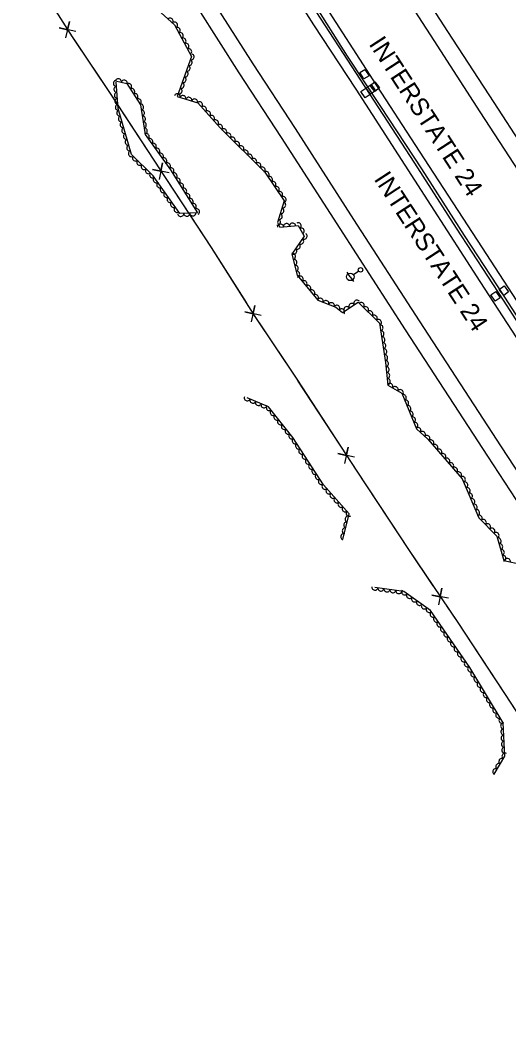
# Model space of a CAD drawing. Extents: x 1746719 to 1766531, y 631721 to 662391.
# Drawn here: x 1758351 to 1758675, y 643107 to 643775 of the extents above; entities that cross this region are included whole.
import ezdxf

# ---------------------------------------------------------------- set-up
doc = ezdxf.new("R2010")
doc.units = 0
for name, color, linetype in [('SURVEY - AERIAL SURVEY - Photo Control - Points - Elevations', 7, 'Continuous'), ('SURVEY - AERIAL SURVEY - Photo Control - Points - Numbers', 7, 'Continuous'), ('SURVEY - AERIAL SURVEY - Photo Control with Text', 7, 'Continuous'), ('SURVEY - CENTERLINE - Existing Roads - Development', 7, 'Continuous'), ('SURVEY - CENTERLINE - Existing Roads Curve Text', 7, 'Continuous'), ('SURVEY - CENTERLINE - Preliminary Curve Text', 7, 'Continuous'), ('SURVEY - CONTROL - Points - Numbers', 7, 'Continuous')]:
    doc.layers.add(name, color=color, linetype=linetype)

msp = doc.modelspace()

# ---------------------------------------------------------------- linework, layer by layer
at = {"layer": 'SURVEY - AERIAL SURVEY - Photo Control - Points - Elevations'}
for points in [[(1758528.06, 643931.93), (1758563.85, 643876.61), (1758601.12, 643819.25), (1758634.52, 643767.49), (1758665.16, 643720.35), (1758703.51, 643661.29), (1758738.55, 643607.32), (1758780.47, 643542.02), (1758810.94, 643495.12), (1758838.28, 643453.17), (1758866.99, 643408.66), (1758892.36, 643369.61), (1758923.55, 643321.11), (1758957.87, 643268.54), (1758994.04, 643213.01), (1759028.02, 643160.29), (1759080.26, 643078.92)], [(1758518.82, 643925.96), (1758554.62, 643870.63), (1758591.89, 643813.27), (1758625.29, 643761.51), (1758655.94, 643714.35), (1758694.29, 643655.3), (1758729.31, 643601.35), (1758771.23, 643536.05), (1758801.72, 643489.13), (1758829.05, 643447.19), (1758857.76, 643402.68), (1758883.12, 643363.64), (1758914.32, 643315.13), (1758948.66, 643262.53), (1758984.81, 643207.03), (1759018.77, 643154.33), (1759063.92, 643084.02)], [(1758478.52, 643899.88), (1758514.34, 643844.52), (1758551.6, 643787.18), (1758585, 643735.42), (1758615.69, 643688.2), (1758654.03, 643629.16), (1758688.99, 643575.32), (1758730.91, 643510.01), (1758761.49, 643462.94), (1758788.78, 643421.08), (1758817.46, 643376.6), (1758842.81, 643337.58), (1758874.04, 643289.02), (1758908.45, 643236.31), (1758944.53, 643180.93), (1758978.4, 643128.37), (1758991.56, 643107.86)], [(1758468.3, 643892.82), (1758518.79, 643814.29), (1758545.64, 643772.07), (1758573.58, 643729.23), (1758612.52, 643668.88), (1758655.85, 643601.7), (1758710.28, 643518.17), (1758755.48, 643448.9), (1758787.26, 643399.75), (1758819.19, 643350.04), (1758852.01, 643299.36), (1758884.04, 643250.16), (1758916.85, 643199.48), (1758947.08, 643151.96), (1758968.19, 643118.54), (1758971.32, 643114.19)], [(1758418.68, 643860.91), (1758469.08, 643782.51), (1758496.04, 643740.12), (1758524.08, 643697.13), (1758562.94, 643636.89), (1758606.35, 643569.6), (1758660.86, 643485.94), (1758706, 643416.76), (1758737.66, 643367.79), (1758769.61, 643318.06), (1758802.52, 643267.23), (1758834.56, 643218.03), (1758867.2, 643167.62), (1758883.89, 643141.38)], [(1758427.93, 643866.86), (1758478.35, 643788.43), (1758505.29, 643746.07), (1758533.31, 643703.11), (1758572.18, 643642.86), (1758615.58, 643575.58), (1758670.07, 643491.95), (1758715.22, 643422.76), (1758746.91, 643373.75), (1758778.85, 643324.02), (1758811.75, 643273.22), (1758843.78, 643224.02), (1758876.46, 643173.56), (1758900.11, 643136.38)]]:
    msp.add_lwpolyline(points, dxfattribs=at)
at = {"layer": 'SURVEY - AERIAL SURVEY - Photo Control - Points - Numbers'}
for points in [[(1758472.93, 643895.91), (1758511.15, 643837.03), (1758541.32, 643789.92), (1758579.58, 643730.89), (1758612.54, 643680.31), (1758640.13, 643637.02), (1758671.38, 643589.3), (1758696.06, 643550.94), (1758734.52, 643491.6), (1758769.46, 643437.46), (1758798.96, 643391.67), (1758828.14, 643347.01), (1758855.82, 643304.89), (1758888.58, 643253.95), (1758919.89, 643205.82), (1758952.75, 643155.4), (1758965.25, 643135.33), (1758978.51, 643110.86)], [(1758474.42, 643896.69), (1758499.1, 643858.3), (1758522.7, 643822.19), (1758544.63, 643788), (1758567.84, 643751.26), (1758589.99, 643717.73), (1758617.15, 643676.37), (1758645.44, 643632.14), (1758667.24, 643598.9), (1758699.36, 643549.24), (1758720.79, 643516.12), (1758745.17, 643478.53), (1758765.34, 643446.49), (1758792.97, 643404.34), (1758817.4, 643366.56), (1758846.78, 643320.84), (1758873.44, 643280.56), (1758895.52, 643246.69), (1758919.66, 643209.23), (1758944.42, 643171.53), (1758969.21, 643133.78), (1758984.79, 643110.37)]]:
    msp.add_lwpolyline(points, dxfattribs=at)
at = {"layer": 'SURVEY - AERIAL SURVEY - Photo Control with Text'}
for points in [[(1758435.74, 643787.95), (1758453.41, 643771.98), (1758464.62, 643750.96), (1758455.18, 643724.33), (1758468.97, 643720.23), (1758483.59, 643703.6), (1758513.21, 643674.18), (1758526.06, 643655.24), (1758521.72, 643640.92), (1758523.21, 643637.84), (1758535.42, 643638.92), (1758539.41, 643631.73), (1758531.29, 643619.91), (1758534.75, 643605.82), (1758548.43, 643589.38), (1758560.33, 643584.66), (1758564.73, 643581.25), (1758575.15, 643588.02), (1758589.31, 643574.05), (1758593.32, 643548.08), (1758594.82, 643533.04), (1758604.05, 643527.55), (1758613.76, 643504.02), (1758621.39, 643497.16), (1758644.23, 643470.72), (1758655.21, 643445), (1758667.15, 643432.88), (1758671.7, 643416.63), (1758684.01, 643414.05)], [(1758414.26, 643734.79), (1758421.69, 643733.15), (1758430.78, 643718.86), (1758433.83, 643699.15), (1758450.77, 643675.7), (1758468.58, 643647.25), (1758456.96, 643646.73), (1758439.28, 643671.92), (1758424.85, 643686.07), (1758416.12, 643716.58), (1758414.67, 643733.96)], [(1758565.06, 643430.47), (1758569.31, 643447.56), (1758552.21, 643466.74), (1758531.82, 643498.33), (1758515.75, 643518.51), (1758501.53, 643524.47)], [(1758665.29, 643274.82), (1758672.43, 643286.87), (1758671.43, 643308.95), (1758649.11, 643345.7), (1758623.16, 643383.41), (1758605.51, 643396.05), (1758586.15, 643398.83)]]:
    msp.add_lwpolyline(points, dxfattribs=at)
for centre, major_axis in [((1758450.54, 643774.58), (1.48, -1.34)), ((1758453.47, 643771.88), (0.94, -1.76)), ((1758455.35, 643768.35), (0.94, -1.76)), ((1758457.24, 643764.82), (0.94, -1.76)), ((1758459.12, 643761.29), (0.94, -1.76)), ((1758461, 643757.76), (0.94, -1.76)), ((1758462.88, 643754.23), (0.94, -1.76)), ((1758463.19, 643746.91), (-0.67, -1.88)), ((1758464.52, 643750.68), (-0.67, -1.88)), ((1758460.51, 643739.37), (-0.67, -1.88)), ((1758461.85, 643743.14), (-0.67, -1.88)), ((1758414.74, 643733.19), (-0.17, 1.99)), ((1758416.21, 643734.36), (1.95, -0.43)), ((1758420.11, 643733.49), (1.95, -0.43)), ((1758422.97, 643731.13), (1.07, -1.69)), ((1758457.84, 643731.83), (-0.67, -1.88)), ((1758459.18, 643735.6), (-0.67, -1.88)), ((1758415.07, 643729.21), (-0.17, 1.99)), ((1758415.4, 643725.22), (-0.17, 1.99)), ((1758425.12, 643727.76), (1.07, -1.69)), ((1758456.5, 643728.06), (-0.67, -1.88)), ((1758415.74, 643721.23), (-0.17, 1.99)), ((1758427.27, 643724.39), (1.07, -1.69)), ((1758429.42, 643721.01), (1.07, -1.69)), ((1758455.22, 643724.32), (1.92, -0.57)), ((1758459.05, 643723.18), (1.92, -0.57)), ((1758462.89, 643722.04), (1.92, -0.57)), ((1758466.72, 643720.9), (1.92, -0.57)), ((1758470.06, 643718.99), (1.32, -1.5)), ((1758416.07, 643717.25), (-0.17, 1.99)), ((1758417.04, 643713.38), (-0.55, 1.92)), ((1758431, 643717.43), (0.31, -1.98)), ((1758431.61, 643713.47), (0.31, -1.98)), ((1758472.7, 643715.98), (1.32, -1.5)), ((1758475.34, 643712.98), (1.32, -1.5)), ((1758418.14, 643709.53), (-0.55, 1.92)), ((1758419.24, 643705.69), (-0.55, 1.92)), ((1758432.22, 643709.52), (0.31, -1.98)), ((1758432.83, 643705.57), (0.31, -1.98)), ((1758477.99, 643709.97), (1.32, -1.5)), ((1758480.63, 643706.97), (1.32, -1.5)), ((1758420.34, 643701.84), (-0.55, 1.92)), ((1758433.44, 643701.61), (0.31, -1.98)), ((1758434.71, 643697.93), (1.17, -1.62)), ((1758483.27, 643703.97), (1.32, -1.5)), ((1758486.08, 643701.13), (1.42, -1.41)), ((1758488.92, 643698.31), (1.42, -1.41)), ((1758421.44, 643698), (-0.55, 1.92)), ((1758422.54, 643694.15), (-0.55, 1.92)), ((1758437.05, 643694.69), (1.17, -1.62)), ((1758439.39, 643691.44), (1.17, -1.62)), ((1758491.76, 643695.49), (1.42, -1.41)), ((1758494.6, 643692.67), (1.42, -1.41)), ((1758423.64, 643690.3), (-0.55, 1.92)), ((1758424.74, 643686.46), (-0.55, 1.92)), ((1758441.73, 643688.2), (1.17, -1.62)), ((1758444.08, 643684.96), (1.17, -1.62)), ((1758497.43, 643689.85), (1.42, -1.41)), ((1758500.27, 643687.03), (1.42, -1.41)), ((1758427.42, 643683.55), (-1.43, 1.4)), ((1758430.27, 643680.75), (-1.43, 1.4)), ((1758446.42, 643681.72), (1.17, -1.62)), ((1758448.76, 643678.48), (1.17, -1.62)), ((1758503.11, 643684.21), (1.42, -1.41)), ((1758505.95, 643681.39), (1.42, -1.41)), ((1758508.79, 643678.58), (1.42, -1.41)), ((1758433.13, 643677.95), (-1.43, 1.4)), ((1758435.99, 643675.15), (-1.43, 1.4)), ((1758438.84, 643672.35), (-1.43, 1.4)), ((1758451.07, 643675.21), (1.06, -1.7)), ((1758453.2, 643671.82), (1.06, -1.7)), ((1758511.62, 643675.76), (1.42, -1.41)), ((1758514.2, 643672.72), (1.12, -1.66)), ((1758441.23, 643669.15), (-1.15, 1.64)), ((1758443.52, 643665.87), (-1.15, 1.64)), ((1758455.32, 643668.43), (1.06, -1.7)), ((1758457.44, 643665.04), (1.06, -1.7)), ((1758516.45, 643669.41), (1.12, -1.66)), ((1758518.69, 643666.1), (1.12, -1.66)), ((1758445.82, 643662.6), (-1.15, 1.64)), ((1758448.12, 643659.33), (-1.15, 1.64)), ((1758459.56, 643661.65), (1.06, -1.7)), ((1758461.69, 643658.26), (1.06, -1.7)), ((1758520.94, 643662.79), (1.12, -1.66)), ((1758523.18, 643659.48), (1.12, -1.66)), ((1758450.42, 643656.05), (-1.15, 1.64)), ((1758452.72, 643652.78), (-1.15, 1.64)), ((1758463.81, 643654.87), (1.06, -1.7)), ((1758465.93, 643651.48), (1.06, -1.7)), ((1758525.43, 643656.17), (1.12, -1.66)), ((1758525.22, 643652.49), (-0.58, -1.91)), ((1758455.01, 643649.51), (-1.15, 1.64)), ((1758457.57, 643646.76), (-2, -0.09)), ((1758461.57, 643646.94), (-2, -0.09)), ((1758465.57, 643647.12), (-2, -0.09)), ((1758468.05, 643648.09), (1.06, -1.7)), ((1758522.9, 643644.83), (-0.58, -1.91)), ((1758524.06, 643648.66), (-0.58, -1.91)), ((1758521.74, 643641), (-0.58, -1.91)), ((1758527.69, 643638.24), (1.99, 0.17)), ((1758531.67, 643638.59), (1.99, 0.17)), ((1758535.54, 643638.71), (0.97, -1.75)), ((1758523.71, 643637.89), (1.99, 0.17)), ((1758537.48, 643635.21), (0.97, -1.75)), ((1758539.39, 643631.71), (-1.13, -1.65)), ((1758534.87, 643625.11), (-1.13, -1.65)), ((1758537.13, 643628.41), (-1.13, -1.65)), ((1758531.69, 643618.27), (0.48, -1.94)), ((1758532.6, 643621.82), (-1.13, -1.65)), ((1758532.65, 643614.39), (0.48, -1.94)), ((1758533.6, 643610.5), (0.48, -1.94)), ((1758534.55, 643606.62), (0.48, -1.94)), ((1758536.78, 643603.38), (1.28, -1.54)), ((1758539.34, 643600.3), (1.28, -1.54)), ((1758541.9, 643597.23), (1.28, -1.54)), ((1758544.46, 643594.15), (1.28, -1.54)), ((1758547.01, 643591.08), (1.28, -1.54)), ((1758550.09, 643588.72), (1.86, -0.74)), ((1758553.81, 643587.24), (1.86, -0.74)), ((1758557.53, 643585.77), (1.86, -0.74)), ((1758570.95, 643585.29), (1.68, 1.09)), ((1758574.3, 643587.47), (1.68, 1.09)), ((1758577.28, 643585.92), (1.42, -1.4)), ((1758561.11, 643584.05), (1.58, -1.23)), ((1758564.27, 643581.6), (1.58, -1.23)), ((1758567.59, 643583.11), (1.68, 1.09)), ((1758580.13, 643583.11), (1.42, -1.4)), ((1758582.97, 643580.3), (1.42, -1.4)), ((1758585.82, 643577.49), (1.42, -1.4)), ((1758588.67, 643574.68), (1.42, -1.4)), ((1758589.78, 643570.98), (0.31, -1.98)), ((1758590.39, 643567.03), (0.31, -1.98)), ((1758591, 643563.08), (0.31, -1.98)), ((1758591.61, 643559.13), (0.31, -1.98)), ((1758592.22, 643555.17), (0.31, -1.98)), ((1758592.83, 643551.22), (0.31, -1.98)), ((1758593.4, 643547.26), (0.2, -1.99)), ((1758593.8, 643543.28), (0.2, -1.99)), ((1758594.2, 643539.3), (0.2, -1.99)), ((1758594.59, 643535.32), (0.2, -1.99)), ((1758596.29, 643532.16), (1.72, -1.02)), ((1758599.73, 643530.12), (1.72, -1.02)), ((1758603.16, 643528.07), (1.72, -1.02)), ((1758605.18, 643524.8), (0.76, -1.85)), ((1758501.64, 643524.43), (-1.84, 0.77)), ((1758505.33, 643522.88), (-1.84, 0.77)), ((1758509.02, 643521.33), (-1.84, 0.77)), ((1758512.71, 643519.79), (-1.84, 0.77)), ((1758606.71, 643521.1), (0.76, -1.85)), ((1758516.19, 643517.97), (-1.25, 1.56)), ((1758518.68, 643514.84), (-1.25, 1.56)), ((1758521.17, 643511.71), (-1.25, 1.56)), ((1758608.23, 643517.41), (0.76, -1.85)), ((1758609.76, 643513.71), (0.76, -1.85)), ((1758523.66, 643508.58), (-1.25, 1.56)), ((1758526.16, 643505.45), (-1.25, 1.56)), ((1758611.29, 643510.01), (0.76, -1.85)), ((1758612.81, 643506.32), (0.76, -1.85)), ((1758528.65, 643502.32), (-1.25, 1.56)), ((1758531.14, 643499.19), (-1.25, 1.56)), ((1758614.89, 643503.01), (1.49, -1.34)), ((1758617.86, 643500.33), (1.49, -1.34)), ((1758620.84, 643497.65), (1.49, -1.34)), ((1758533.4, 643495.89), (-1.08, 1.68)), ((1758535.57, 643492.53), (-1.08, 1.68)), ((1758623.52, 643494.69), (1.31, -1.51)), ((1758626.13, 643491.67), (1.31, -1.51)), ((1758537.73, 643489.17), (-1.08, 1.68)), ((1758539.9, 643485.81), (-1.08, 1.68)), ((1758628.75, 643488.64), (1.31, -1.51)), ((1758631.36, 643485.61), (1.31, -1.51)), ((1758542.07, 643482.45), (-1.08, 1.68)), ((1758544.24, 643479.09), (-1.08, 1.68)), ((1758633.98, 643482.59), (1.31, -1.51)), ((1758636.59, 643479.56), (1.31, -1.51)), ((1758546.41, 643475.73), (-1.08, 1.68)), ((1758548.58, 643472.37), (-1.08, 1.68)), ((1758639.21, 643476.53), (1.31, -1.51)), ((1758641.82, 643473.51), (1.31, -1.51)), ((1758550.75, 643469.01), (-1.08, 1.68)), ((1758553.08, 643465.77), (-1.33, 1.49)), ((1758644.36, 643470.43), (0.79, -1.84)), ((1758645.93, 643466.75), (0.79, -1.84)), ((1758555.74, 643462.78), (-1.33, 1.49)), ((1758558.4, 643459.79), (-1.33, 1.49)), ((1758647.5, 643463.07), (0.79, -1.84)), ((1758649.07, 643459.39), (0.79, -1.84)), ((1758561.06, 643456.81), (-1.33, 1.49)), ((1758563.72, 643453.82), (-1.33, 1.49)), ((1758650.64, 643455.71), (0.79, -1.84)), ((1758652.21, 643452.03), (0.79, -1.84)), ((1758566.39, 643450.84), (-1.33, 1.49)), ((1758568.44, 643444.06), (0.48, 1.94)), ((1758569.05, 643447.85), (-1.33, 1.49)), ((1758653.78, 643448.35), (0.79, -1.84)), ((1758655.46, 643444.75), (1.4, -1.42)), ((1758567.48, 643440.18), (0.48, 1.94)), ((1758658.26, 643441.9), (1.4, -1.42)), ((1758661.07, 643439.05), (1.4, -1.42)), ((1758565.55, 643432.41), (0.48, 1.94)), ((1758566.51, 643436.3), (0.48, 1.94)), ((1758663.88, 643436.2), (1.4, -1.42)), ((1758666.68, 643433.35), (1.4, -1.42)), ((1758668.05, 643429.66), (0.54, -1.93)), ((1758669.13, 643425.81), (0.54, -1.93)), ((1758670.21, 643421.96), (0.54, -1.93)), ((1758671.29, 643418.11), (0.54, -1.93)), ((1758674.12, 643416.13), (1.96, -0.41)), ((1758586.3, 643398.81), (-1.98, 0.28)), ((1758590.26, 643398.24), (-1.98, 0.28)), ((1758594.22, 643397.67), (-1.98, 0.28)), ((1758598.18, 643397.1), (-1.98, 0.28)), ((1758602.14, 643396.54), (-1.98, 0.28)), ((1758605.99, 643395.71), (-1.63, 1.16)), ((1758609.24, 643393.38), (-1.63, 1.16)), ((1758612.5, 643391.05), (-1.63, 1.16)), ((1758615.75, 643388.72), (-1.63, 1.16)), ((1758619, 643386.39), (-1.63, 1.16)), ((1758622.25, 643384.06), (-1.63, 1.16)), ((1758624.79, 643381.03), (-1.13, 1.65)), ((1758627.06, 643377.74), (-1.13, 1.65)), ((1758629.33, 643374.44), (-1.13, 1.65)), ((1758631.6, 643371.15), (-1.13, 1.65)), ((1758633.86, 643367.85), (-1.13, 1.65)), ((1758636.13, 643364.56), (-1.13, 1.65)), ((1758638.4, 643361.26), (-1.13, 1.65)), ((1758640.67, 643357.97), (-1.13, 1.65)), ((1758642.93, 643354.67), (-1.13, 1.65)), ((1758645.2, 643351.38), (-1.13, 1.65)), ((1758647.47, 643348.08), (-1.13, 1.65)), ((1758649.68, 643344.75), (-1.04, 1.71)), ((1758651.76, 643341.33), (-1.04, 1.71)), ((1758653.84, 643337.91), (-1.04, 1.71)), ((1758655.91, 643334.5), (-1.04, 1.71)), ((1758657.99, 643331.08), (-1.04, 1.71)), ((1758660.07, 643327.66), (-1.04, 1.71)), ((1758662.14, 643324.24), (-1.04, 1.71)), ((1758664.22, 643320.82), (-1.04, 1.71)), ((1758666.3, 643317.4), (-1.04, 1.71)), ((1758668.37, 643313.98), (-1.04, 1.71)), ((1758670.45, 643310.56), (-1.04, 1.71)), ((1758671.53, 643306.84), (-0.09, 2)), ((1758671.71, 643302.85), (-0.09, 2)), ((1758671.89, 643298.85), (-0.09, 2)), ((1758672.07, 643294.85), (-0.09, 2)), ((1758672.25, 643290.86), (-0.09, 2)), ((1758672.43, 643286.86), (1.02, 1.72)), ((1758668.35, 643279.98), (1.02, 1.72)), ((1758670.39, 643283.42), (1.02, 1.72)), ((1758666.31, 643276.54), (1.02, 1.72))]:
    msp.add_ellipse(centre, major_axis=major_axis, ratio=0.940188, start_param=0, end_param=3.141593, dxfattribs=at)
at = {"layer": 'SURVEY - CENTERLINE - Existing Roads - Development'}
for p, q in [((1758569.95, 643604.79), (1758567.84, 643607.89)), ((1758575.53, 643608.58), (1758572.01, 643606.19)), ((1758569.95, 643604.79), (1758572.05, 643601.68))]:
    msp.add_line(p, q, dxfattribs=at)
for centre, radius in [((1758569.95, 643604.79), 2.5), ((1758576.77, 643609.42), 1.5)]:
    msp.add_circle(centre, radius, dxfattribs=at)
at = {"layer": 'SURVEY - CENTERLINE - Existing Roads Curve Text'}
for points in [[(1758351.04, 643818.32), (1758385.57, 643764.03), (1758411.6, 643725.11), (1758447.68, 643669.95), (1758477.76, 643624.19), (1758506.67, 643578.6), (1758534.41, 643536.82), (1758573.88, 643476.45), (1758608.56, 643423.99), (1758641.16, 643375.4), (1758672.61, 643327.81), (1758704.48, 643278.87)], [(1758387.93, 643767.6), (1758376.94, 643769.97), (1758382.46, 643768.74), (1758383.69, 643774.27), (1758381.18, 643763.31)], [(1758386.55, 643762.58), (1758411.6, 643725.11), (1758412.33, 643724)], [(1758412.33, 643724), (1758439.7, 643682.15)], [(1758449.86, 643673.74), (1758438.84, 643675.97), (1758444.38, 643674.82), (1758445.54, 643680.35), (1758443.17, 643669.36)], [(1758448.52, 643668.68), (1758474, 643629.91)], [(1758474, 643629.91), (1758477.76, 643624.19), (1758500.87, 643587.74)], [(1758510.91, 643579.19), (1758499.93, 643581.58), (1758505.45, 643580.34), (1758506.68, 643585.86), (1758504.16, 643574.91)], [(1758509.59, 643574.21), (1758534.41, 643536.82), (1758535.25, 643535.55)], [(1758535.25, 643535.55), (1758562.6, 643493.7)], [(1758572.76, 643485.28), (1758561.74, 643487.52), (1758567.28, 643486.36), (1758568.44, 643491.89), (1758566.07, 643480.91)], [(1758571.41, 643480.22), (1758573.88, 643476.45), (1758596.99, 643441.5)], [(1758596.99, 643441.5), (1758608.56, 643423.99), (1758624.72, 643399.9)], [(1758634.98, 643391.61), (1758623.94, 643393.71), (1758629.49, 643392.62), (1758630.58, 643398.17), (1758628.34, 643387.15)], [(1758633.69, 643386.53), (1758641.16, 643375.4), (1758659.35, 643347.87)], [(1758659.35, 643347.87), (1758672.61, 643327.81), (1758686.77, 643306.06)]]:
    msp.add_lwpolyline(points, dxfattribs=at)
at = {"layer": 'SURVEY - CENTERLINE - Preliminary Curve Text'}
for p, q in [((1758579.33, 643739.25), (1758579.33, 643739.25)), ((1758580, 643726.76), (1758580, 643726.76)), ((1758583.51, 643729.15), (1758583.51, 643729.15)), ((1758586.26, 643731.01), (1758586.26, 643731.01)), ((1758671.82, 643595.67), (1758671.82, 643595.67)), ((1758666.17, 643591.83), (1758666.17, 643591.83))]:
    msp.add_line(p, q, dxfattribs=at)
for points in [[(1758576.31, 643740.3), (1758579.69, 643742.43), (1758582.36, 643738.2), (1758578.98, 643736.07), (1758576.31, 643740.3)], [(1758583.15, 643731.77), (1758586.31, 643734.21), (1758589.37, 643730.26), (1758586.21, 643727.81), (1758583.15, 643731.77)], [(1758576.94, 643727.71), (1758580.25, 643729.95), (1758583.05, 643725.82), (1758579.75, 643723.57), (1758576.94, 643727.71)], [(1758580.45, 643730.09), (1758583.76, 643732.34), (1758586.57, 643728.2), (1758583.26, 643725.95), (1758580.45, 643730.09)], [(1758663.11, 643592.78), (1758666.42, 643595.03), (1758669.23, 643590.89), (1758665.92, 643588.64), (1758663.11, 643592.78)], [(1758668.71, 643596.44), (1758671.89, 643598.87), (1758674.93, 643594.9), (1758671.75, 643592.46), (1758668.71, 643596.44)]]:
    msp.add_lwpolyline(points, dxfattribs=at)

# ---------------------------------------------------------------- texts
at = {"layer": 'SURVEY - CONTROL - Points - Numbers'}
for rotation, p in [(302.99561, (1758581.91, 643759.33)), (303.07163, (1758585.27, 643669.7))]:
    msp.add_text('INTERSTATE 24', height=12, rotation=rotation, dxfattribs=at).set_placement(p)

doc.saveas('drawing.dxf')
